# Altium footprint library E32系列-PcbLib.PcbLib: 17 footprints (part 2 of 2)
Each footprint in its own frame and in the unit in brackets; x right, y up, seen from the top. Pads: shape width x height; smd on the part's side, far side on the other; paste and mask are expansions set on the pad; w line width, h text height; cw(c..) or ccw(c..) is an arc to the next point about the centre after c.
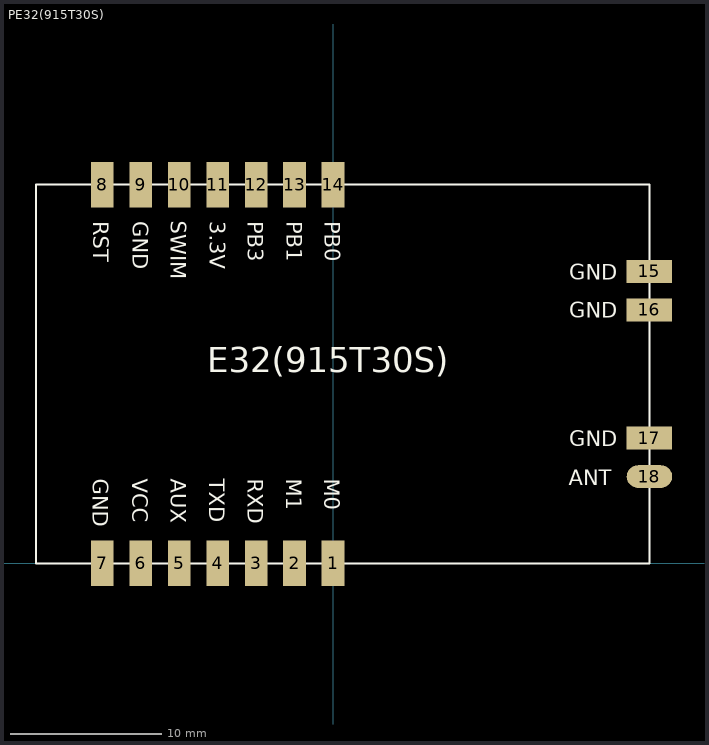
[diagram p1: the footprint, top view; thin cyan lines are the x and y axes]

## PE32(915T30S) [mm] "40.5mm*25mm*3.80mm-S"
pads (18):
  rect 1.5x3 smd: 1(0,0) 2(-2.54,0) 3(-5.08,0) 4(-7.62,0) 5(-10.16,0) 6(-12.7,0) 7(-15.24,0) 8(-15.24,25) 9(-12.7,25) 10(-10.16,25) 11(-7.62,25) 12(-5.08,25) 13(-2.54,25) 14(0,25)
  rect 3x1.5 smd: 15(20.88,19.27) 16(20.88,16.73) 17(20.88,8.27)
  oval 3x1.5 smd: 18(20.88,5.73)
Top Overlay:
  lines w0.127: -19.62,0 -19.62,25 20.88,25 20.88,0 -19.62,0
  text "E32(915T30S)" at -8.317,12.065 h2.8
  text "GND" at 15.602,7.72 h1
  text "ANT" at 15.554,5.17 h1
  text "M0" at -0.577,5.575 h1
  text "M1" at -3.087,5.575 h1
  text "RXD" at -5.637,5.575 h1
  text "TXD" at -8.167,5.575 h1
  text "AUX" at -10.707,5.575 h1
  text "VCC" at -13.257,5.575 h1
  text "GND" at -15.847,5.575 h1
  text "RST" at -15.827,22.592 h1
  text "GND" at -13.237,22.592 h1
  text "3.3V" at -8.147,22.592 h1
  text "PB3" at -5.617,22.592 h1
  text "PB1" at -3.067,22.592 h1
  text "PB0" at -0.557,22.592 h1
  text "GND" at 15.602,16.22 h1
  text "GND" at 15.602,18.73 h1
  text "SWIM" at -10.73,22.606 h1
